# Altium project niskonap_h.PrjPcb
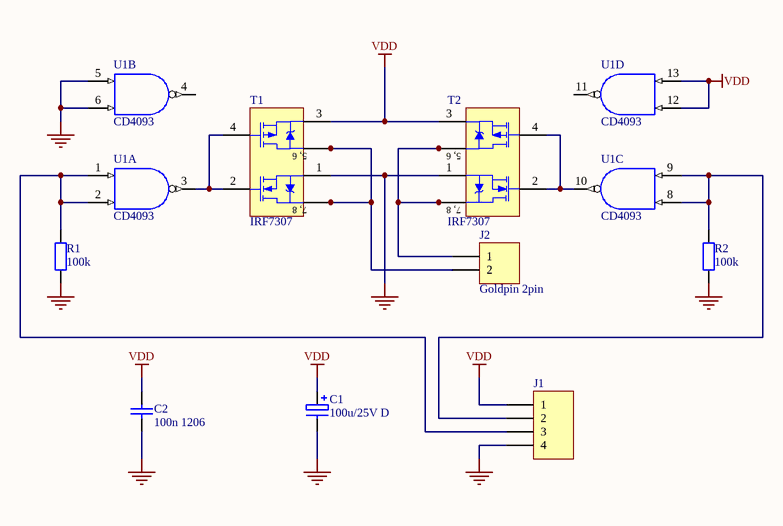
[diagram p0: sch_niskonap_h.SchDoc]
1 sheet, 9 parts. Net scope: global (net labels, ports and power ports of the same name join across sheets).
Board file: pcb_niskonap_h.PcbDoc

## Sheet sch_niskonap_h.SchDoc
size A4

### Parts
C1  100u/25V D  [D SMD elektrolit]
C2  100n 1206  [MELF-1206]
J1  Goldpin 4pin  [HDR1X4]  (value not drawn)
J2  Goldpin 2pin  [HDR1X2]
R1  100k  [MELF-1206]
R2  100k  [MELF-1206]
T1  IRF7307  [SO-8_N]
T2  IRF7307  [SO-8_N]
U1  CD4093  [751A-03_N]  (parts A,B,C,D of 4)

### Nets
GND: C1.2 C2.1 J1.4 R1.1 R2.1 T1.1(S1) T2.1(S1) U1.5(A) U1.6(B) U1.7(GND)
VDD: C1.1 C2.2 J1.1 T1.3(S2) T2.3(S2) U1.12(A) U1.13(B) U1.14(VDD)
NetJ1_2: J1.2 R2.2 U1.8(A) U1.9(B)
NetJ1_3: J1.3 R1.2 U1.1(A) U1.2(B)
NetJ2_1: J2.1 T2.5(D2) T2.6(D2) T2.7(D1) T2.8(D1)
NetJ2_2: J2.2 T1.5(D2) T1.6(D2) T1.7(D1) T1.8(D1)
NetT1_2: T1.2(G1) T1.4(G2) U1.3(~{Y})
NetT2_2: T2.2(G1) T2.4(G2) U1.10(~{Y})

Not connected (* = marked no-connect by the designer): U1 4(~{Y}) 11(~{Y})

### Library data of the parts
C1 = kond biegunowy: Polarized Capacitor
C2 = kondensator
J1 = Header 4: Header, 4-Pin
J2 = Header 2: Header, 2-Pin
R1 R2 = rezystor
T1 T2 = IRF7307: HEXFET Power MOSFET
U1 = MC14093BD: Quad 2-Input NAND Schmitt Trigger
